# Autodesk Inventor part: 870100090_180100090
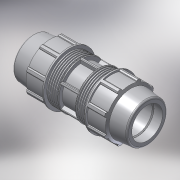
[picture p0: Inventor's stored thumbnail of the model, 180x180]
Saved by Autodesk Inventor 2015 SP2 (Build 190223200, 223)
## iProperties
Created: 2017-02
Part Number: 870100090_180100090
Material: PVC-Piping
Description: PLASSON COUPLER 90-90
Document SubType Name: Modeling
Designer: KIM
Mass: 2387.75 g
Surface Area: 2478.17 cm^2
Volume: 1705.54 cm^3
Density: 1.4 g/cm^3
Appearance: Smooth - White
Author: KIM
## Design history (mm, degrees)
derived "87010.ipt"
feature "Solid1::87010.ipt"
tag "TaggingFeature1"
body "Solid1"
other parameters: "d1" = 334, "d4" = 27.83333, "d5" = 47.71429, "d7" = 152, "d8" = 114, "d9" = 47.71429, "d11" = 4.77143, "d12" = 121.6, "d13" = 120 deg, "d14" = 117, "d15" = 6 deg, "d16" = 136.8, "d18" = 4.5, "d19" = 35 deg, "d20" = 17.5 deg, "d21" = 141.36, "d23" = 0, "d25" = 360 deg, "d27" = 3.04, "d33" = 1.8, "d34" = 7.6, "d36" = 0, "d37" = 1.8, "d38" = 1.8, "d40" = 360 deg, "d42" = 60.12, "d46" = 2.7, "d50" = 4.175, "d51" = 0, "d53" = 3.05371, "d54" = 3.05371, "d57" = 6.10743, "d62" = 134.064, "d64" = 81, "d65" = 164, "E_" = 152, "H_" = 334, "l_" = 164, "d52" = 30.53714
